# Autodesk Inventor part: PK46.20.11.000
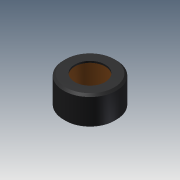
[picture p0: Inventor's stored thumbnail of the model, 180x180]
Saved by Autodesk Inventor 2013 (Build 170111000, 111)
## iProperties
Created: 2012-02
Part Number: PK46.20.11.000
Material: Silicone
Document SubType Name: Modeling
Designer: tedescj
Mass: 18.6674 g
Surface Area: 71.6929 cm^2
Volume: 14.934 cm^3
Density: 1.25 g/cm^3
Author: tedescj
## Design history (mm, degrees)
derived "PK46.20.10.000.ipt"
feature "Stitch Surface1"
combine "Combine2"
  body "Solid3"
feature "PK46.20.11.000::PK46.20.10.000.ipt" dims "d0" = 10
tag "TaggingFeature1"
body "Solid1"
feature "Composite1"
body "Srf1"
